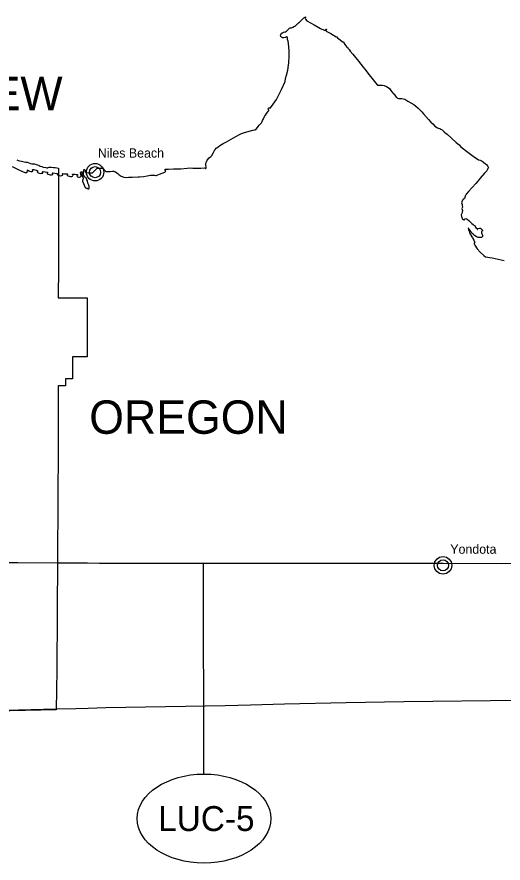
# Model space of a CAD drawing. Extents: x 0 to 750, y 0 to 507.
# Drawn here: x 461 to 515.6, y 219.2 to 314.3 of the extents above; entities that cross this region are included whole.
import ezdxf

# ---------------------------------------------------------------- set-up
doc = ezdxf.new("R2010")
doc.units = 0
for name, color, linetype in [('DV_X_Corp_Line', 7, 'Continuous'), ('GM_P_US_Alignment', 7, 'Continuous'), ('GM_X_Corporation_Text', 7, 'Continuous'), ('GM_X_County', 7, 'Continuous'), ('GM_X_State_Route', 7, 'Continuous'), ('SH_Data', 7, 'Continuous')]:
    doc.layers.add(name, color=color, linetype=linetype)

msp = doc.modelspace()

# ---------------------------------------------------------------- linework, layer by layer
at = {"layer": 'DV_X_Corp_Line'}
msp.add_lwpolyline([(461.027, 298.239), (461.186, 298.183), (461.361, 298.136), (461.541, 298.115), (461.696, 298.074), (461.855, 298.038), (462.035, 298.006), (462.195, 297.98), (462.365, 297.919), (462.538, 297.852), (462.714, 297.821), (462.879, 297.815), (463.009, 297.784), (463.178, 297.738), (463.348, 297.696), (463.518, 297.63), (463.657, 297.554), (463.827, 297.487), (463.992, 297.446), (464.276, 297.384), (464.406, 297.358), (464.491, 297.357), (464.536, 297.392), (464.636, 297.437), (464.861, 297.425), (465.136, 297.388), (465.321, 297.377), (465.516, 297.335), (465.683, 297.315), (465.686, 286.145), (465.674, 282.737), (468.934, 282.738), (468.936, 276.125), (467.277, 276.124), (467.278, 273.64), (466.472, 273.64), (466.473, 272.845), (465.65, 272.847), (465.657, 266.104), (465.509, 240.945), (465.444, 236.442), (437.863, 235.873)], dxfattribs=at)
for centre, radius in [((469.812, 296.864), 0.982), ((469.812, 296.864), 0.623), ((508.896, 252.693), 0.982), ((508.896, 252.693), 0.623)]:
    msp.add_circle(centre, radius, dxfattribs=at)
at = {"layer": 'GM_P_US_Alignment'}
msp.add_line((465.798, 252.987), (495.54, 252.937), dxfattribs=at)
at = {"layer": 'GM_X_County'}
for points in [[(460.503, 297.485), (461.308, 297.095), (461.902, 296.823), (462.073, 296.817), (462.131, 296.836), (462.164, 296.865), (462.215, 297.072), (462.232, 297.107), (462.28, 297.117), (462.338, 297.027), (462.425, 296.991), (462.6, 296.933), (462.732, 296.949), (462.813, 296.994), (462.816, 297.033), (462.797, 297.091), (462.794, 297.137), (462.836, 297.159), (462.923, 297.149), (463.288, 297.059), (463.353, 297.036), (463.362, 296.991), (463.33, 296.959), (463.307, 296.939), (463.311, 296.907), (463.424, 296.807), (463.715, 296.726), (463.828, 296.736), (463.931, 296.771), (463.937, 296.81), (463.912, 296.875), (463.915, 296.914), (463.963, 296.933), (464.425, 296.875), (464.448, 296.865), (464.483, 296.826), (464.458, 296.784), (464.429, 296.762), (464.438, 296.723), (464.538, 296.639), (464.748, 296.565), (464.929, 296.568), (465.046, 296.613), (465.055, 296.668), (465.026, 296.723), (465.029, 296.755), (465.078, 296.788), (465.556, 296.729), (465.588, 296.707), (465.601, 296.684), (465.579, 296.636), (465.559, 296.603), (465.582, 296.571), (465.694, 296.513), (465.789, 296.477), (465.934, 296.452), (466.057, 296.474), (466.16, 296.526), (466.189, 296.584), (466.18, 296.616), (466.144, 296.645), (466.147, 296.684), (466.189, 296.704), (466.373, 296.691), (466.435, 296.681), (466.667, 296.662), (466.716, 296.636), (466.726, 296.607), (466.716, 296.581), (466.674, 296.552), (466.677, 296.529), (466.742, 296.461), (466.887, 296.403), (467.026, 296.377), (467.152, 296.39), (467.265, 296.429), (467.327, 296.477), (467.336, 296.529), (467.294, 296.561), (467.275, 296.594), (467.288, 296.629), (467.33, 296.642), (467.391, 296.642), (467.527, 296.626), (467.824, 296.6), (467.853, 296.568), (467.85, 296.519), (467.824, 296.497), (467.766, 296.497), (467.753, 296.455), (467.782, 296.403), (467.84, 296.339), (467.934, 296.319), (468.07, 296.322), (468.16, 296.355), (468.247, 296.413), (468.234, 296.477), (468.205, 296.597), (468.189, 296.833), (468.209, 296.901), (468.26, 296.904), (468.305, 296.888), (468.338, 296.813), (468.338, 296.655), (468.377, 296.442), (468.461, 296.177), (468.461, 296.099), (468.425, 296.028), (468.393, 295.915), (468.396, 295.864), (468.687, 295.146), (468.729, 295.124), (468.855, 295.069), (468.935, 295.059), (468.974, 295.046), (469.01, 294.982), (469.084, 294.978), (469.091, 295.011), (469.129, 295.088), (469.155, 295.156), (469.142, 295.285), (469.107, 295.411), (469, 295.634), (468.981, 295.705), (468.974, 295.783), (468.945, 295.893), (468.884, 296.022), (468.793, 296.213), (468.771, 296.264), (468.648, 296.319), (468.609, 296.39), (468.564, 296.507), (468.522, 296.675), (468.512, 296.859), (468.532, 297.133), (468.567, 297.169), (468.632, 297.169), (468.671, 297.143), (468.68, 297.088), (468.671, 296.956), (468.68, 296.914), (468.716, 296.868), (468.816, 296.817), (469.042, 296.788), (469.514, 296.791), (470.044, 297.305), (470.677, 297.301), (471.032, 296.943), (471.507, 296.943), (471.762, 296.962), (471.908, 296.972), (471.969, 296.943), (472.098, 296.894), (472.24, 296.794), (472.35, 296.72), (472.431, 296.626), (472.502, 296.565), (472.735, 296.416), (473.042, 296.309), (473.287, 296.274), (473.559, 296.287), (473.975, 296.322), (474.641, 296.339), (474.793, 296.335), (475.264, 296.384), (475.649, 296.458), (476.03, 296.532), (476.289, 296.539), (476.473, 296.519), (476.631, 296.494), (476.728, 296.503), (476.848, 296.555), (477.061, 296.623), (477.348, 296.755), (477.642, 296.875), (477.723, 296.952), (477.742, 297.017), (477.717, 297.062), (477.662, 297.075), (477.649, 297.124), (477.675, 297.162), (477.726, 297.185), (478.075, 297.211), (478.628, 297.227), (479.442, 297.256), (480.14, 297.324), (480.492, 297.337), (480.808, 297.321), (481.345, 297.298), (481.678, 297.314), (482.055, 297.347), (482.162, 297.324), (482.204, 297.269), (482.265, 297.279), (482.285, 297.34), (482.291, 297.418), (482.265, 297.66), (482.262, 297.86), (482.317, 298.041), (482.414, 298.228), (482.637, 298.461), (482.802, 298.616), (482.912, 298.723), (483.13, 299.061), (483.154, 299.136), (483.18, 299.233), (483.238, 299.295), (483.241, 299.33), (483.251, 299.366), (483.348, 299.437), (483.425, 299.56), (483.503, 299.614), (483.651, 299.728), (483.835, 299.87), (484.21, 300.093), (484.588, 300.283), (485.635, 300.871), (486.042, 301.084), (486.262, 301.198), (486.482, 301.288), (486.863, 301.398), (487.528, 301.582), (487.755, 301.634), (487.924, 301.722), (488.136, 301.979), (488.246, 302.138), (488.336, 302.267), (488.504, 302.409), (488.543, 302.483), (488.611, 302.677), (488.711, 302.874), (488.824, 303.104), (488.943, 303.278), (489.082, 303.446), (489.205, 303.64), (489.315, 303.789), (489.325, 303.837), (489.292, 303.889), (489.26, 303.96), (489.276, 304.047), (489.321, 304.083), (489.376, 304.092), (489.454, 304.066), (489.489, 304.066), (489.645, 304.26), (490.187, 305.026), (490.32, 305.268), (490.759, 306.15), (491.144, 307.068), (491.215, 307.375), (491.315, 307.772), (491.447, 308.321), (491.538, 308.88), (491.57, 309.142), (491.589, 309.339), (491.619, 309.701), (491.615, 310.505), (491.554, 311.319), (491.493, 311.584), (491.438, 311.769), (491.425, 311.995), (491.412, 312.024), (491.318, 312.085), (491.195, 312.008), (490.995, 311.966), (490.859, 311.969), (490.746, 312.024), (490.659, 312.127), (490.646, 312.253), (490.678, 312.337), (490.779, 312.473), (490.846, 312.505), (490.992, 312.602), (491.124, 312.634), (491.215, 312.641), (491.305, 312.696), (491.412, 312.831), (491.661, 313.045), (491.735, 313.093), (491.877, 313.09), (492.029, 313.145), (492.2, 313.255), (492.291, 313.287), (492.497, 313.503), (492.646, 313.633), (492.778, 313.71), (492.982, 313.927), (493.247, 314.195), (493.392, 314.295), (493.447, 314.308), (493.457, 314.247), (493.434, 314.188), (493.418, 314.127), (493.463, 314.049), (493.602, 313.885), (494.436, 313.432), (495.124, 313.025), (495.537, 312.838), (495.644, 312.815), (495.699, 312.87), (495.76, 312.945), (495.789, 312.938), (495.789, 312.909), (495.741, 312.812), (495.78, 312.722), (496.287, 312.444), (496.875, 312.079), (496.93, 312.079), (496.994, 312.079), (497.02, 312.03), (497.059, 311.962), (497.356, 311.723), (497.57, 311.536), (497.618, 311.51), (497.699, 311.497), (497.728, 311.475), (497.754, 311.384), (497.883, 311.206), (498.096, 310.925), (498.138, 310.906), (498.18, 310.906), (498.212, 310.809), (498.345, 310.631), (498.468, 310.467), (498.749, 310.114), (499.382, 309.32), (499.912, 308.677), (500.122, 308.425), (500.594, 307.795), (501.056, 307.223), (501.488, 306.683), (501.521, 306.651), (501.595, 306.648), (501.847, 306.651), (502.096, 306.632), (502.29, 306.599), (502.551, 306.509), (502.742, 306.393), (502.897, 306.257), (503.046, 306.053), (503.146, 305.882), (503.333, 305.672), (503.401, 305.62), (503.637, 305.304), (503.692, 305.246), (503.789, 305.188), (503.912, 305.155), (504.254, 305.139), (504.419, 305.116), (504.596, 305.055), (504.936, 304.861), (505.294, 304.674), (505.621, 304.464), (505.814, 304.315), (506.086, 304.063), (506.515, 303.663), (506.719, 303.414), (507.268, 302.79), (507.53, 302.487), (507.733, 302.286), (507.982, 302.041), (508.27, 301.837), (508.396, 301.811), (508.531, 301.769), (508.657, 301.711), (508.787, 301.634), (508.909, 301.524), (509.01, 301.401), (509.287, 301.188), (509.317, 301.156), (509.856, 300.69), (510.389, 300.215), (510.69, 299.947), (510.909, 299.731), (511.678, 299.123), (512.276, 298.648), (512.883, 298.27), (513.064, 298.212), (513.29, 298.102), (513.617, 297.854), (513.833, 297.673), (513.901, 297.589), (513.982, 297.434), (513.985, 297.369), (513.937, 297.292), (513.888, 297.204), (513.846, 297.095), (513.801, 297.017), (513.568, 296.739), (513.067, 296.196), (512.938, 296.057), (512.809, 295.86), (512.573, 295.592), (511.753, 294.71), (511.491, 294.397), (511.381, 294.177), (511.297, 293.925), (511.158, 293.802), (511.084, 293.702), (511.019, 293.541), (510.987, 293.434), (511.032, 293.234), (511.058, 293.134), (511.064, 292.943), (511.006, 292.794), (511.068, 292.562), (511.061, 292.371), (511, 292.223), (510.938, 292.067), (510.967, 291.867), (511.097, 291.583), (511.232, 291.505), (511.3, 291.518), (511.323, 291.576), (511.371, 291.631), (511.468, 291.647), (511.62, 291.583), (511.778, 291.45), (512.027, 291.211), (512.127, 291.114), (512.266, 290.969), (512.347, 290.908), (512.418, 290.885), (512.489, 290.827), (512.505, 290.743), (512.557, 290.678), (512.605, 290.588), (512.657, 290.565), (512.683, 290.52), (512.731, 290.488), (512.738, 290.439), (512.757, 290.433), (512.786, 290.459), (512.857, 290.523), (512.99, 290.575), (513.103, 290.575), (513.139, 290.552), (513.151, 290.491), (513.203, 290.452), (513.255, 290.426), (513.313, 290.355), (513.345, 290.316), (513.326, 290.281), (513.303, 290.281), (513.258, 290.232), (513.226, 290.119), (513.226, 290.045), (513.261, 289.955), (513.307, 289.851), (513.355, 289.728), (513.345, 289.706), (513.332, 289.661), (513.339, 289.625), (513.294, 289.583), (513.239, 289.544), (513.213, 289.531), (513.193, 289.509), (513.151, 289.515), (513.122, 289.538), (512.906, 289.531), (512.848, 289.531), (512.777, 289.557), (512.728, 289.557), (512.602, 289.651), (512.425, 289.761), (512.392, 289.796), (512.282, 289.893), (512.147, 290.013), (512.04, 290.168), (511.904, 290.333), (511.833, 290.452), (511.772, 290.523), (511.749, 290.568), (511.72, 290.559), (511.74, 290.507), (511.762, 290.391), (511.782, 290.329), (511.837, 290.236), (511.885, 290.087), (511.953, 289.887), (512.056, 289.745), (512.053, 289.703), (512.131, 289.602), (512.218, 289.473), (512.231, 289.425), (512.337, 289.231), (512.463, 288.972), (512.408, 288.901), (512.395, 288.863), (512.405, 288.817), (512.486, 288.675), (512.748, 288.242), (513.067, 287.877), (513.471, 287.493), (513.662, 287.36), (514.415, 287.254), (514.764, 287.163), (515.772, 286.943)], [(517.503, 237.497), (504.506, 237.374), (498.028, 237.23), (491.089, 237.082), (487.262, 237), (484.412, 236.922), (471.015, 236.669), (469.99, 236.64), (469.018, 236.617), (467.636, 236.578), (465.456, 236.546), (455.564, 236.266), (448.32, 236.095), (441.996, 235.937), (437.867, 235.85), (429.652, 235.896), (425.577, 235.908), (408.562, 235.712), (403.124, 235.652)]]:
    msp.add_lwpolyline(points, dxfattribs=at)
at = {"layer": 'GM_X_State_Route'}
for points in [[(442.401, 253.159), (452.401, 253.058), (455.711, 253.024), (461.133, 253.007), (465.594, 252.988), (465.666, 252.988)], [(465.666, 252.988), (465.798, 252.987)], [(465.798, 252.987), (468.971, 252.973)], [(468.971, 252.973), (470.292, 252.956)], [(470.292, 252.956), (471.481, 252.94)], [(471.481, 252.94), (471.539, 252.94), (472.586, 252.923), (472.934, 252.922)], [(472.934, 252.922), (482.315, 252.906), (495.54, 252.937)], [(495.54, 252.937), (508.898, 252.947), (515.509, 252.905), (522.235, 252.989)]]:
    msp.add_lwpolyline(points, dxfattribs=at)
at = {"layer": 'SH_Data'}
msp.add_line((482.024, 229.242), (481.979, 252.905), dxfattribs=at)
msp.add_ellipse((482.046, 224.242), major_axis=(7.5, 0), ratio=0.666667, dxfattribs=at)

# ---------------------------------------------------------------- texts
at = {"layer": 'DV_X_Corp_Line'}
for s, height, p in [('Niles Beach', 1.04167, (470.123, 298.498)), ('Yondota', 1.0417, (509.709, 253.994))]:
    msp.add_text(s, height=height, rotation=0.00001, dxfattribs=at).set_placement(p)
at = {"layer": 'GM_X_Corporation_Text'}
for s, height, p in [('HARBOR VIEW', 3.75007, (430.493, 303.829)), ('OREGON', 3.7501, (469.155, 267.472))]:
    msp.add_text(s, height=height, rotation=0.00001, dxfattribs=at).set_placement(p)
at = {"layer": 'SH_Data'}
msp.add_text('LUC-5', height=2.8, dxfattribs=at).set_placement((476.901, 222.842))

doc.saveas('drawing.dxf')
